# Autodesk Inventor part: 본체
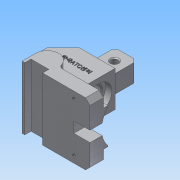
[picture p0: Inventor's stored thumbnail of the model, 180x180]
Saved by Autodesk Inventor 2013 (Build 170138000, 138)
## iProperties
Created: 2016-11
Part Number: 본체
Material: 알루미늄 6061
Document SubType Name: Modeling
Designer: Administrator
Density: 2.71 g/cm^3
Mass: 462.906 g
Surface Area: 317.29 cm^2
Volume: 170.814 cm^3
Author: Administrator
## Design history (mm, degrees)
sketch "스케치1"
  geometry: 1 further point
sketch "스케치2"
  geometry: L1 (-13, 0)-(-13, -15); L2 (13, 0)-(63, 0); L3 (63, 0)-(63, -15); L4 (-13, -15)-(-10, -15); L5 (-10, -15)-(-10, -8); L6 (-10, -8)-(10, -8); L7 (10, -8)-(10, -15); L8 (10, -15)-(63, -15); A1 r 13 centre (0, 0) between (12.488, 3.611) and (-13, 0); A2 r 5 centre (17.292, 5) between (12.488, 3.611) and (17.292, 0); 1 further point
  constraints: 16 end point, 4 perpendicular, 4 point on circle, 3 tangent, 2 centre point, 2 parallel, 1 coincident, 1 horizontal alignment, 1 point on line, 1 vertical
  dimensions: "d0" = 26 diameter of A1; "d1" = 15 distance of L1.start L1.end; "d2" = 10 diameter of A2; "d3" = 63 distance of L2.end point (0, 0); "d5" = 15 distance of L2.end L3.end; "d6" = 3 distance of L1.end L4.end; "d7" = 7 distance of L4.end L5.end; "d8" = 20 distance of L5.end L6.end; "d9" = 7 distance of L6.end L7.end; "d10" = 50 distance of L2.start L2.end
extrude "돌출1" new body sketch "스케치2" distance "d11" = 15; taper "d12" = 0 deg
chamfer "모따기1" distance "d13" = 5; stored, may be unused: second distance "d14" = 2, angle "d15" = 45 deg
node "작업 평면1"
sketch "스케치4"
  geometry: L1 (-13, -15)-(-13, 0) reference; L2 (17.292, 0)-(63, 0) reference; L3 (63, 0)-(63, -15) reference; L4 (63, -15)-(10, -15) reference; L5 (10, -15)-(10, -8) reference; L6 (10, -8)-(-10, -8) reference; L7 (-10, -8)-(-10, -15) reference; L8 (-10, -15)-(-13, -15) reference; A1 r 13 centre (0, 0) between (12.488, 3.611) and (-13, 0) reference; A2 r 5 centre (17.292, 5) between (12.488, 3.611) and (17.292, 0) reference; 1 further point
extrude "돌출2" join sketch "스케치4" distance "d21" = 15; taper "d22" = 0 deg
chamfer "모따기2" distance "d23" = 5; stored, may be unused: second distance "d24" = 2, angle "d25" = 45 deg
sketch "스케치5"
  geometry: L1 (0, 0)-(-10, 0) reference; L2 (0, 15)-(0, 0) reference; L3 (0, 15)-(-10, 15) reference; L4 (0, 15)-(0, 20); L5 (50, 15)-(50, 0) reference; L6 (50, 15)-(40, 15) reference; L7 (40, 0)-(40, 15) reference; L8 (50, 0)-(40, 0) reference; L9 (40, 15)-(40, 20); L10 (-15, 15)-(-15, 0) reference; L11 (0, 20)-(1.106, 20); L12 (40, 20)-(38.894, 20); L13 (14, 0)-(14, 13.627); L14 (26, 0)-(26, 13.627); L15 (0, 0)-(14, 0); L16 (26, 0)-(40, 0); A1 r 29 centre (20, 42) between (1.106, 20) and (14, 13.627); A2 r 29 centre (20, 42) between (26, 13.627) and (38.894, 20)
  constraints: 16 end point, 5 perpendicular, 4 point on circle, 3 parallel, 2 centre point, 1 collinear
  dimensions: "d27" = 5 distance of L2.start L4.end; "d28" = 5 distance of L6.end L9.end; "d29" = 42 distance from line of L1 A1.centre; "d30" = 35 distance from line of L10 A1.centre; "d31" = 6 horizontal distance of A1.centre L13.start; "d32" = 6 distance from line of L14 A1.centre; "d33" = 29 radius of A1; "d34" = 29 radius of A2
extrude "돌출3" join sketch "스케치5" distance "d35" = 18; taper "d36" = 0 deg
sketch "스케치7"
  geometry: L1 (-40, 20)-(-40, 15) reference; L2 (-40, 0)-(-40, 15) reference; L3 (-40, 0)-(-26, 0) reference; L4 (-40, 20)-(-40, 0); L5 (0, 20)-(0, 15) reference; L6 (-40, 20)-(0, 20); L7 (0, 0)-(-40, 0); L8 (0, 20)-(0, 0)
  constraints: 8 end point, 2 collinear, 2 perpendicular, 1 point on line
extrude "돌출4" join sketch "스케치7" distance "d38" = 58; taper "d39" = 0 deg
node "작업 평면6"
sketch "스케치11"
  geometry: L1 (10, 20)-(10, 28) reference; L2 (10, 20)-(50, 20) reference; L3 (50, 28)-(50, 20) reference; L4 (10, 20)-(10, 60); L5 (10, 60)-(50, 60); L6 (50, 60)-(50, 20); L7 (65, 0)-(-5, 0) reference; 1 further point
  constraints: 6 end point, 1 parallel, 1 perpendicular
  dimensions: "d55" = 40 distance of L4.end L5.end; "d56" = 60 distance between parallel lines of L7 L5
extrude "돌출7" join sketch "스케치11" distance "d57" = 58; taper "d58" = 0 deg
sketch "스케치12"
  geometry: L1 (0, 40)-(0, 0) reference; L2 (0, 40)-(-58, 40) reference; L3 (-58, 0)-(-58, 40) reference; L4 (0, 0)-(-58, 0) reference; 1 further point
extrude "돌출8" join sketch "스케치12" distance "d59" = 48; taper "d60" = 0 deg
chamfer "모따기4" distance "d61" = 18; stored, may be unused: second distance "d62" = 2, angle "d63" = 45 deg
chamfer "모따기5" distance "d64" = 4; stored, may be unused: second distance "d65" = 2, angle "d66" = 45 deg
sketch "스케치13"
  geometry: L1 (50, 60)-(10, 60) reference; L2 (-5, 0)-(0, 0) reference; 3 further points
  constraints: 1 midpoint, 1 vertical alignment
  dimensions: "d67" = 42 distance from line of L2 point (30, 42)
hole "구멍1" sketch "스케치13" at (30, 42) diameter "d68" = 20; stored, may be unused: countersink angle "d72" = 90 deg, drill point angle "d74" = 118 deg; dims "d69" = 6, "d70" = 29, "d71" = 7, "d73" = 8
chamfer "모따기7" distance "d78" = 1; stored, may be unused: second distance "d79" = 2, angle "d80" = 45 deg
sketch "스케치14"
  geometry: L1 (20, -7)-(20, 0) reference; L2 (20, 0)-(0, 0) reference; L3 (0, 0)-(0, -7) reference; L4 (20, -7)-(0, -7) reference; 1 further point
extrude "돌출9" cut sketch "스케치14" stored distance "d81" = 48; taper "d82" = 0 deg
node "작업 평면7"
sketch "스케치15"
  geometry: L1 (10, 60)-(50, 60) reference; L2 (20, 60)-(20, 90); L3 (20, 90)-(40, 90); L4 (40, 90)-(40, 60); L5 (65, 0)-(-5, 0) reference; 3 further points
  constraints: 6 end point, 3 perpendicular, 2 midpoint, 2 point on line, 1 vertical alignment
  dimensions: "d84" = 20 distance of L2.end L3.end; "d85" = 90 distance between parallel lines of L5 L3
extrude "돌출10" join sketch "스케치15" distance "d86" = 25; taper "d87" = 0 deg
chamfer "모따기8" distance "d88" = 4; stored, may be unused: second distance "d89" = 2, angle "d90" = 45 deg
sketch "스케치17"
  geometry: L1 (45.708, 15)-(45.708, 5) reference; L2 (40.708, 0)-(0, 0) reference; L3 (27.708, 41)-(27.708, 29) reference; L4 (40.708, 70)-(-7.292, 70) reference; 3 further points
  constraints: 1 vertical alignment
  dimensions: "d103" = 18 distance from line of point (27.708, 7.5) L1; "d104" = 7.5 distance from line of L2 point (27.708, 7.5); "d105" = 7.5 distance from line of L4 point (27.708, 62.5)
hole "구멍3" sketch "스케치17" at (27.708, 7.5), (27.708, 62.5) diameter "d106" = 3.242; stored, may be unused: countersink angle "d110" = 90 deg, drill point angle "d112" = 118 deg; dims "d107" = 30, "d108" = 29, "d109" = 7, "d111" = 30
sketch "스케치18"
  geometry: L1 (-32, 45)-(-32, 5) reference; L2 (-32, 45)-(-72, 45) reference; 1 further point
  constraints: 1 other
  dimensions: "d113" = 25 distance from line of L1 point (-57, 27); "d114" = 18 distance from line of point (-57, 27) L2
feature "엠보싱1" sketch "스케치18" dims "d0" = 26, "d1" = 15, "d2" = 10, "d3" = 63, "d5" = 15, "d6" = 3, "d7" = 7, "d8" = 20, "d9" = 7, "d10" = 50, "d115" = 0.5, "d116" = 0
fillet "모깎기1" dims "d117" = 3
sketch "스케치19"
  geometry: L1 (-4, -27)-(-4, -4) reference; L2 (5, -90)-(53, -90) reference; C1 r 4 at (8.5, -13); 1 further point
  constraints: 1 centre point
  dimensions: "d118" = 8 diameter of C1; "d119" = 77 distance from line of L2 C1.centre; "d120" = 12.5 distance from line of L1 C1.centre
extrude "돌출11" cut sketch "스케치19" distance "d121" = 30; taper "d122" = 0 deg
chamfer "모따기10" distance "d123" = 1; stored, may be unused: second distance "d124" = 2, angle "d125" = 45 deg
node "솔리드1"
node "투영된 루프1"
node "투영된 루프2"
other parameters: "d26" = 58, "d54" = -32, "d83" = -5
